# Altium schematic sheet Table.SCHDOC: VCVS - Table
size A
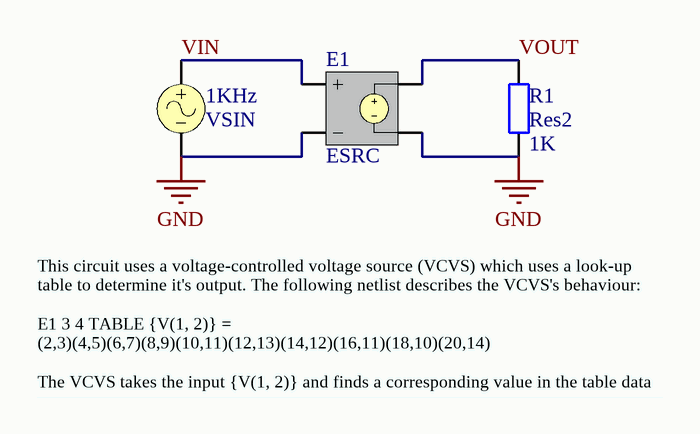
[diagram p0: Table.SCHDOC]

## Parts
1KHz  VSIN
E1  ESRC
R1  Res2  value 1K  [AXIAL-0.4]

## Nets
GND: 1KHz.2 E1.2(NC-) E1.4(N-) R1.1
VIN: 1KHz.1 E1.1(NC+)
VOUT: E1.3(N+) R1.2

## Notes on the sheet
- This circuit uses a voltage-controlled voltage source (VCVS) which uses a look-up table to determine it's output. The following netlist describes the VCVS's behaviour:
  E1 3 4 TABLE {V(1, 2)} = (2,3)(4,5)(6,7)(8,9)(10,11)(12,13)(14,12)(16,11)(18,10)(20,14)
  The VCVS takes the input {V(1, 2)} and finds a corresponding value in the table data and uses this as it's output.

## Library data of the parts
1KHz = VSIN: Sinusoidal Voltage Source; Note: PCB Footprint - Not required
E1 = ESRC: Voltage Controlled Voltage Source; Note: PCB Footprint - Not required; Sim Note: Enter gain into gain field
R1 = Res2: Resistor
